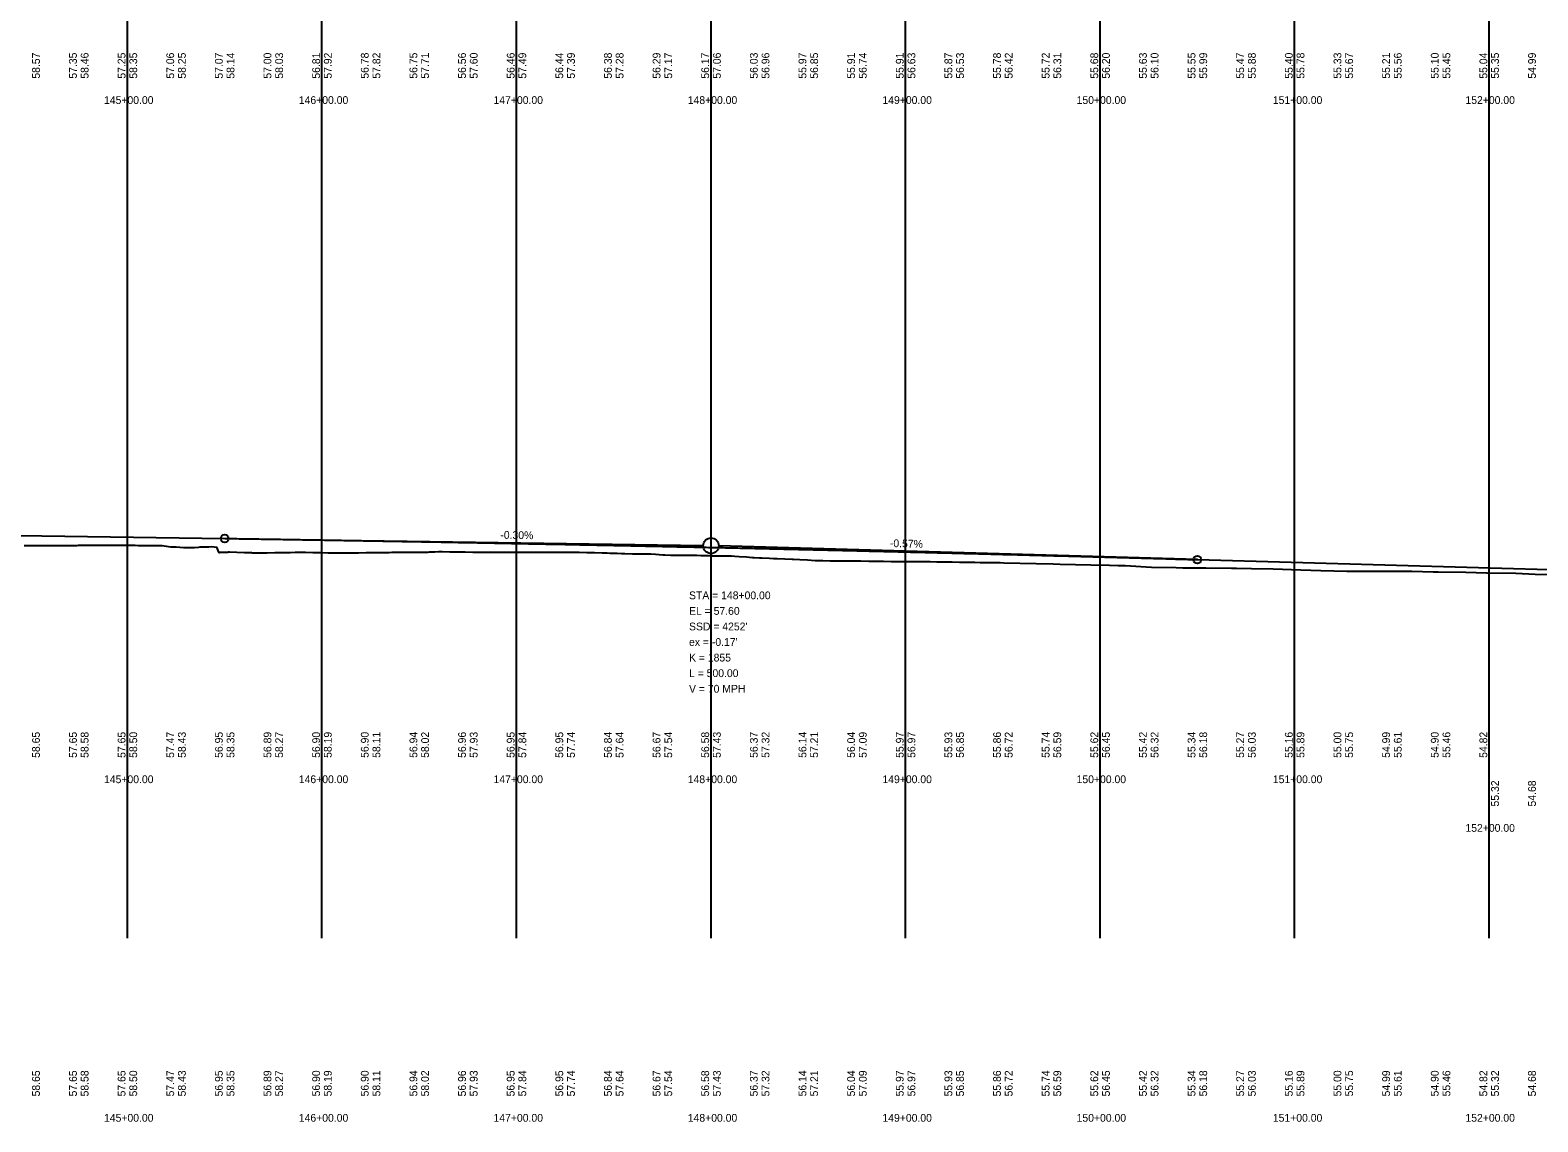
# Model space of a CAD drawing. Extents: x 3880794 to 3915434, y 287517 to 300173.
# Drawn here: x 3913601 to 3914376, y 292382 to 292943 of the extents above; entities that cross this region are included whole.
import ezdxf

# ---------------------------------------------------------------- set-up
doc = ezdxf.new("R2010")
doc.units = 0
for name, color, linetype in [('Level 1', 7, 'Continuous'), ('Level 30', 7, 'Continuous'), ('Level 31', 7, 'Continuous'), ('Level 32', 7, 'Continuous')]:
    doc.layers.add(name, color=color, linetype=linetype)

msp = doc.modelspace()

# ---------------------------------------------------------------- linework, layer by layer
at = {"layer": 'Level 1'}
for p, q in [((3913651.21, 292476.49), (3913651.21, 293504.13)), ((3913751.21, 292476.49), (3913751.21, 293504.13)), ((3913851.21, 292476.49), (3913851.21, 293504.13)), ((3913951.21, 292476.49), (3913951.21, 293504.13)), ((3914051.21, 292476.49), (3914051.21, 293504.13)), ((3914151.21, 292476.49), (3914151.21, 293504.13)), ((3914251.21, 292476.49), (3914251.21, 293504.13)), ((3914351.21, 292476.49), (3914351.21, 293504.13)), ((3913401.21, 292686.36), (3913701.21, 292681.86)), ((3913701.21, 292681.86), (3913947.21, 292678.17)), ((3914201.21, 292670.99), (3913955.21, 292678)), ((3914201.21, 292670.99), (3914552.78, 292660.98))]:
    msp.add_line(p, q, dxfattribs=at)
for points in [[(3913598.07, 292678.27), (3913601.89, 292678.23), (3913605.8, 292678.24), (3913609.71, 292678.26), (3913613.62, 292678.31), (3913617.53, 292678.3), (3913621.44, 292678.31), (3913625.35, 292678.33), (3913626.01, 292678.34), (3913628.74, 292678.38), (3913629.26, 292678.38), (3913633.17, 292678.37), (3913637.09, 292678.37), (3913641, 292678.39), (3913641.31, 292678.39), (3913642.66, 292678.37), (3913644.91, 292678.36), (3913648.82, 292678.34), (3913652.73, 292678.34), (3913655.2, 292678.35), (3913656.65, 292678.31), (3913660.55, 292678.27), (3913664.46, 292678.25), (3913668.37, 292678.25), (3913669.06, 292678.25), (3913672.28, 292677.77), (3913673.54, 292677.59), (3913676.19, 292677.48), (3913680.1, 292677.22), (3913680.77, 292677.18), (3913684.02, 292677.16), (3913685.68, 292677.15), (3913687.93, 292677.45), (3913688.68, 292677.56), (3913691.84, 292677.59), (3913693.07, 292677.61), (3913694.36, 292677.68), (3913695.75, 292677.53), (3913696.94, 292677.42), (3913698.03, 292674.77), (3913698.46, 292674.72), (3913698.97, 292674.77), (3913699.66, 292674.8), (3913701.44, 292674.89), (3913702.47, 292674.88)], [(3913702.47, 292674.88), (3913702.78, 292674.85), (3913703.1, 292674.94), (3913703.68, 292675.03), (3913707.48, 292674.87), (3913711.39, 292674.71), (3913714.91, 292674.57), (3913715.3, 292674.54), (3913717.98, 292674.4), (3913719.21, 292674.42), (3913723.12, 292674.5), (3913727.03, 292674.58), (3913730.95, 292674.66), (3913734.86, 292674.73), (3913737.39, 292674.78), (3913737.75, 292674.78), (3913738.77, 292674.8), (3913739.37, 292674.81), (3913740.12, 292674.8), (3913742.68, 292674.76), (3913746.59, 292674.69), (3913750.5, 292674.63), (3913754.41, 292674.56), (3913758.32, 292674.49), (3913762.23, 292674.42), (3913762.76, 292674.41), (3913763.37, 292674.43), (3913766.14, 292674.47), (3913770.05, 292674.53), (3913773.96, 292674.58), (3913777.88, 292674.63), (3913781.79, 292674.68), (3913783.74, 292674.69), (3913785.7, 292674.73), (3913787.05, 292674.76), (3913789.61, 292674.77), (3913793.52, 292674.77), (3913797.43, 292674.78), (3913801.34, 292674.79), (3913805.25, 292674.8), (3913805.88, 292674.8), (3913806.5, 292674.94), (3913807.08, 292674.96), (3913809.16, 292675.04), (3913811.06, 292675.12), (3913813.07, 292675.09), (3913816.98, 292675.04), (3913820.89, 292674.99), (3913824.8, 292674.94), (3913828.72, 292674.88), (3913831.94, 292674.83), (3913832.63, 292674.83), (3913836.54, 292674.84), (3913837.4, 292674.84), (3913840.45, 292674.84), (3913844.36, 292674.85), (3913848.27, 292674.85), (3913852.18, 292674.85), (3913855.01, 292674.85), (3913856.09, 292674.86), (3913860, 292674.89), (3913862.01, 292674.9), (3913863.91, 292674.9), (3913867.82, 292674.9), (3913871.73, 292674.9), (3913873.09, 292674.89), (3913875.65, 292674.87), (3913879.56, 292674.84), (3913882.02, 292674.82), (3913883.47, 292674.78), (3913887.38, 292674.69), (3913891.29, 292674.59), (3913895.2, 292674.49), (3913897.74, 292674.42), (3913899.11, 292674.39), (3913899.81, 292674.37), (3913903.02, 292674.22), (3913905.17, 292674.12), (3913906.93, 292674.1), (3913910.84, 292674.04), (3913914.75, 292673.99), (3913918.66, 292673.93), (3913920.2, 292673.91), (3913922.58, 292673.72), (3913926.49, 292673.42), (3913926.96, 292673.38), (3913927.48, 292673.38), (3913930.4, 292673.35), (3913934.31, 292673.31), (3913935.21, 292673.3), (3913938.22, 292673.27), (3913942.13, 292673.23), (3913943.87, 292673.21), (3913946.04, 292673.15), (3913949.95, 292673.03), (3913951.86, 292672.98), (3913952.93, 292672.94), (3913953.86, 292672.96), (3913954.42, 292672.97), (3913957.77, 292672.92), (3913961.68, 292672.86)], [(3913961.68, 292672.86), (3913963.5, 292672.83), (3913965.59, 292672.67), (3913969.51, 292672.37), (3913972.47, 292672.14), (3913973.42, 292672.09), (3913976.05, 292671.95), (3913977.33, 292671.88), (3913981.24, 292671.66), (3913983.27, 292671.54), (3913985.15, 292671.49), (3913989.1, 292671.36), (3913992.97, 292671.3), (3913993.54, 292671.29), (3913996.88, 292671.08), (3914000.79, 292670.84), (3914004.7, 292670.59), (3914005.34, 292670.55), (3914008.61, 292670.5), (3914012.52, 292670.45), (3914016.44, 292670.4), (3914018.47, 292670.37), (3914020.35, 292670.34), (3914024.26, 292670.31), (3914028.17, 292670.28), (3914032.37, 292670.25), (3914035.99, 292670.18), (3914039.9, 292670.12), (3914043.81, 292670.05), (3914044.79, 292670.03), (3914045.16, 292670.03), (3914047.72, 292669.99), (3914048.78, 292669.97), (3914051.63, 292669.96), (3914055.54, 292669.96), (3914059.45, 292669.95), (3914062.69, 292669.94), (3914063.36, 292669.94), (3914063.88, 292669.94), (3914067.28, 292669.89), (3914071.19, 292669.83), (3914073.15, 292669.8), (3914075.1, 292669.77), (3914079.01, 292669.72), (3914082.92, 292669.67), (3914086.83, 292669.62), (3914089.62, 292669.58), (3914090.74, 292669.57), (3914097.74, 292669.46), (3914099.76, 292669.43), (3914101.74, 292669.38), (3914118.25, 292669.01), (3914127.04, 292668.78), (3914130.68, 292668.7), (3914146.48, 292668.31), (3914155.99, 292668.07), (3914160.46, 292667.95), (3914164.09, 292667.9), (3914177.58, 292667.13), (3914190.27, 292666.97), (3914193.78, 292666.8), (3914205.54, 292666.78), (3914218.81, 292666.61), (3914221.3, 292666.61), (3914228.94, 292666.41), (3914240.14, 292666.19), (3914254.37, 292665.82), (3914264.66, 292665.39), (3914278.05, 292665.04), (3914289.44, 292665.1), (3914295.64, 292665.07), (3914297.41, 292665.08), (3914311.45, 292665.01), (3914322.36, 292664.71), (3914324.91, 292664.64), (3914339.28, 292664.57), (3914349.76, 292664.23), (3914350.1, 292664.22), (3914364.82, 292663.98), (3914374.84, 292663.54), (3914388.56, 292663.32)]]:
    msp.add_lwpolyline(points, dxfattribs=at)
msp.add_circle((3913951.21, 292678.11), 4, dxfattribs=at)
msp.add_spline([(3913701.21, 292681.86), (3913711.21, 292681.71), (3913721.21, 292681.55), (3913731.21, 292681.4), (3913741.21, 292681.24), (3913751.21, 292681.08), (3913761.21, 292680.91), (3913771.21, 292680.74), (3913781.21, 292680.57), (3913791.21, 292680.4), (3913801.21, 292680.22), (3913811.21, 292680.05), (3913821.21, 292679.86), (3913831.21, 292679.68), (3913841.21, 292679.49), (3913851.21, 292679.31), (3913861.21, 292679.11), (3913871.21, 292678.92), (3913881.21, 292678.72), (3913891.21, 292678.52), (3913901.21, 292678.32), (3913911.21, 292678.11), (3913921.21, 292677.91), (3913931.21, 292677.7), (3913941.21, 292677.48), (3913951.21, 292677.27), (3913961.21, 292677.05), (3913971.21, 292676.83), (3913981.21, 292676.6), (3913991.21, 292676.38), (3914001.21, 292676.15), (3914011.21, 292675.91), (3914021.21, 292675.68), (3914031.21, 292675.44), (3914041.21, 292675.2), (3914051.21, 292674.96), (3914061.21, 292674.71), (3914071.21, 292674.46), (3914081.21, 292674.21), (3914091.21, 292673.96), (3914101.21, 292673.7), (3914111.21, 292673.44), (3914121.21, 292673.18), (3914131.21, 292672.92), (3914141.21, 292672.65), (3914151.21, 292672.38), (3914161.21, 292672.11), (3914171.21, 292671.83), (3914181.21, 292671.55), (3914191.21, 292671.27), (3914201.21, 292670.99)], degree=3, dxfattribs=at)
at = {"layer": 'Level 31'}
for centre in [(3913701.21, 292681.86), (3914201.21, 292670.99)]:
    msp.add_circle(centre, 2, dxfattribs=at)

# ---------------------------------------------------------------- texts
at = {"layer": 'Level 30'}
for s, p in [('145+00.00', (3913639.18, 292905.16)), ('145+00.00', (3913639.18, 292905.16)), ('146+00.00', (3913739.31, 292905.16)), ('146+00.00', (3913739.31, 292905.16)), ('147+00.00', (3913839.4, 292905.16)), ('147+00.00', (3913839.4, 292905.16)), ('148+00.00', (3913939.25, 292905.16)), ('148+00.00', (3913939.25, 292905.16)), ('149+00.00', (3914039.31, 292905.16)), ('149+00.00', (3914039.31, 292905.16)), ('150+00.00', (3914139.12, 292905.16)), ('150+00.00', (3914139.12, 292905.16)), ('151+00.00', (3914240, 292905.16)), ('151+00.00', (3914240, 292905.16)), ('152+00.00', (3914338.99, 292905.16)), ('152+00.00', (3914338.99, 292905.16)), ('145+00.00', (3913639.18, 292556.11)), ('145+00.00', (3913639.18, 292556.11)), ('146+00.00', (3913739.31, 292556.11)), ('146+00.00', (3913739.31, 292556.11)), ('147+00.00', (3913839.4, 292556.11)), ('147+00.00', (3913839.4, 292556.11)), ('148+00.00', (3913939.25, 292556.11)), ('148+00.00', (3913939.25, 292556.11)), ('149+00.00', (3914039.31, 292556.11)), ('149+00.00', (3914039.31, 292556.11)), ('150+00.00', (3914139.12, 292556.11)), ('150+00.00', (3914139.12, 292556.11)), ('151+00.00', (3914240, 292556.11)), ('151+00.00', (3914240, 292556.11)), ('152+00.00', (3914338.99, 292531.11)), ('152+00.00', (3914338.99, 292531.11)), ('145+00.00', (3913639.18, 292382.11)), ('145+00.00', (3913639.18, 292382.11)), ('146+00.00', (3913739.31, 292382.11)), ('146+00.00', (3913739.31, 292382.11)), ('147+00.00', (3913839.4, 292382.11)), ('147+00.00', (3913839.4, 292382.11)), ('148+00.00', (3913939.25, 292382.11)), ('148+00.00', (3913939.25, 292382.11)), ('149+00.00', (3914039.31, 292382.11)), ('149+00.00', (3914039.31, 292382.11)), ('150+00.00', (3914139.12, 292382.11)), ('150+00.00', (3914139.12, 292382.11)), ('151+00.00', (3914240, 292382.11)), ('151+00.00', (3914240, 292382.11)), ('152+00.00', (3914338.99, 292382.11)), ('152+00.00', (3914338.99, 292382.11))]:
    msp.add_text(s, height=4, dxfattribs=at).set_placement(p)
at = {"layer": 'Level 31'}
for s, rotation, p in [('-0.30%', 359.14063, (3913842.88, 292681.73)), ('-0.57%', 358.3687, (3914043.11, 292677.49)), ('58.65', 90, (3913606.21, 292569.11)), ('57.65', 90, (3913625.21, 292569.11)), ('58.58', 90, (3913631.21, 292569.11)), ('57.65', 90, (3913650.21, 292569.11)), ('58.50', 90, (3913656.21, 292569.11)), ('57.47', 90, (3913675.21, 292569.11)), ('58.43', 90, (3913681.21, 292569.11)), ('56.95', 90, (3913700.21, 292569.11)), ('58.35', 90, (3913706.21, 292569.11)), ('56.89', 90, (3913725.21, 292569.11)), ('58.27', 90, (3913731.21, 292569.11)), ('56.90', 90, (3913750.21, 292569.11)), ('58.19', 90, (3913756.21, 292569.11)), ('56.90', 90, (3913775.21, 292569.11)), ('58.11', 90, (3913781.21, 292569.11)), ('56.94', 90, (3913800.21, 292569.11)), ('58.02', 90, (3913806.21, 292569.11)), ('56.96', 90, (3913825.21, 292569.11)), ('57.93', 90, (3913831.21, 292569.11)), ('56.95', 90, (3913850.21, 292569.11)), ('57.84', 90, (3913856.21, 292569.11)), ('56.95', 90, (3913875.21, 292569.11)), ('57.74', 90, (3913881.21, 292569.11)), ('56.84', 90, (3913900.21, 292569.11)), ('57.64', 90, (3913906.21, 292569.11)), ('56.67', 90, (3913925.21, 292569.11)), ('57.54', 90, (3913931.21, 292569.11)), ('56.58', 90, (3913950.21, 292569.11)), ('57.43', 90, (3913956.21, 292569.11)), ('56.37', 90, (3913975.21, 292569.11)), ('57.32', 90, (3913981.21, 292569.11)), ('56.14', 90, (3914000.21, 292569.11)), ('57.21', 90, (3914006.21, 292569.11)), ('56.04', 90, (3914025.21, 292569.11)), ('57.09', 90, (3914031.21, 292569.11)), ('55.97', 90, (3914050.21, 292569.11)), ('56.97', 90, (3914056.21, 292569.11)), ('55.93', 90, (3914075.21, 292569.11)), ('56.85', 90, (3914081.21, 292569.11)), ('55.86', 90, (3914100.21, 292569.11)), ('56.72', 90, (3914106.21, 292569.11)), ('55.74', 90, (3914125.21, 292569.11)), ('56.59', 90, (3914131.21, 292569.11)), ('55.62', 90, (3914150.21, 292569.11)), ('56.45', 90, (3914156.21, 292569.11)), ('55.42', 90, (3914175.21, 292569.11)), ('56.32', 90, (3914181.21, 292569.11)), ('55.34', 90, (3914200.21, 292569.11)), ('56.18', 90, (3914206.21, 292569.11)), ('55.27', 90, (3914225.21, 292569.11)), ('56.03', 90, (3914231.21, 292569.11)), ('55.16', 90, (3914250.21, 292569.11)), ('55.89', 90, (3914256.21, 292569.11)), ('55.00', 90, (3914275.21, 292569.11)), ('55.75', 90, (3914281.21, 292569.11)), ('54.99', 90, (3914300.21, 292569.11)), ('55.61', 90, (3914306.21, 292569.11)), ('54.90', 90, (3914325.21, 292569.11)), ('55.46', 90, (3914331.21, 292569.11)), ('54.82', 90, (3914350.21, 292569.11)), ('55.32', 90, (3914356.21, 292544.11)), ('54.68', 90, (3914375.21, 292544.11)), ('58.65', 90, (3913606.21, 292395.11)), ('57.65', 90, (3913625.21, 292395.11)), ('58.58', 90, (3913631.21, 292395.11)), ('57.65', 90, (3913650.21, 292395.11)), ('58.50', 90, (3913656.21, 292395.11)), ('57.47', 90, (3913675.21, 292395.11)), ('58.43', 90, (3913681.21, 292395.11)), ('56.95', 90, (3913700.21, 292395.11)), ('58.35', 90, (3913706.21, 292395.11)), ('56.89', 90, (3913725.21, 292395.11)), ('58.27', 90, (3913731.21, 292395.11)), ('56.90', 90, (3913750.21, 292395.11)), ('58.19', 90, (3913756.21, 292395.11)), ('56.90', 90, (3913775.21, 292395.11)), ('58.11', 90, (3913781.21, 292395.11)), ('56.94', 90, (3913800.21, 292395.11)), ('58.02', 90, (3913806.21, 292395.11)), ('56.96', 90, (3913825.21, 292395.11)), ('57.93', 90, (3913831.21, 292395.11)), ('56.95', 90, (3913850.21, 292395.11)), ('57.84', 90, (3913856.21, 292395.11)), ('56.95', 90, (3913875.21, 292395.11)), ('57.74', 90, (3913881.21, 292395.11)), ('56.84', 90, (3913900.21, 292395.11)), ('57.64', 90, (3913906.21, 292395.11)), ('56.67', 90, (3913925.21, 292395.11)), ('57.54', 90, (3913931.21, 292395.11)), ('56.58', 90, (3913950.21, 292395.11)), ('57.43', 90, (3913956.21, 292395.11)), ('56.37', 90, (3913975.21, 292395.11)), ('57.32', 90, (3913981.21, 292395.11)), ('56.14', 90, (3914000.21, 292395.11)), ('57.21', 90, (3914006.21, 292395.11)), ('56.04', 90, (3914025.21, 292395.11)), ('57.09', 90, (3914031.21, 292395.11)), ('55.97', 90, (3914050.21, 292395.11)), ('56.97', 90, (3914056.21, 292395.11)), ('55.93', 90, (3914075.21, 292395.11)), ('56.85', 90, (3914081.21, 292395.11)), ('55.86', 90, (3914100.21, 292395.11)), ('56.72', 90, (3914106.21, 292395.11)), ('55.74', 90, (3914125.21, 292395.11)), ('56.59', 90, (3914131.21, 292395.11)), ('55.62', 90, (3914150.21, 292395.11)), ('56.45', 90, (3914156.21, 292395.11)), ('55.42', 90, (3914175.21, 292395.11)), ('56.32', 90, (3914181.21, 292395.11)), ('55.34', 90, (3914200.21, 292395.11)), ('56.18', 90, (3914206.21, 292395.11)), ('55.27', 90, (3914225.21, 292395.11)), ('56.03', 90, (3914231.21, 292395.11)), ('55.16', 90, (3914250.21, 292395.11)), ('55.89', 90, (3914256.21, 292395.11)), ('55.00', 90, (3914275.21, 292395.11)), ('55.75', 90, (3914281.21, 292395.11)), ('54.99', 90, (3914300.21, 292395.11)), ('55.61', 90, (3914306.21, 292395.11)), ('54.90', 90, (3914325.21, 292395.11)), ('55.46', 90, (3914331.21, 292395.11)), ('54.82', 90, (3914350.21, 292395.11)), ('55.32', 90, (3914356.21, 292395.11)), ('54.68', 90, (3914375.21, 292395.11))]:
    msp.add_text(s, height=4, rotation=rotation, dxfattribs=at).set_placement(p)
for s, p in [('STA = 148+00.00', (3913939.9, 292650.63)), ('EL = 57.60', (3913939.9, 292642.63)), ("SSD = 4252'", (3913939.9, 292634.63)), ("ex = -0.17'", (3913939.9, 292626.63)), ('K = 1855', (3913939.9, 292618.63)), ('L = 500.00', (3913939.9, 292610.63)), ('V = 70 MPH', (3913939.9, 292602.63))]:
    msp.add_text(s, height=4, dxfattribs=at).set_placement(p)
at = {"layer": 'Level 32'}
for s, p in [('58.57', (3913606.21, 292918.16)), ('57.35', (3913625.21, 292918.16)), ('58.46', (3913631.21, 292918.16)), ('57.25', (3913650.21, 292918.16)), ('58.35', (3913656.21, 292918.16)), ('57.06', (3913675.21, 292918.16)), ('58.25', (3913681.21, 292918.16)), ('57.07', (3913700.21, 292918.16)), ('58.14', (3913706.21, 292918.16)), ('57.00', (3913725.21, 292918.16)), ('58.03', (3913731.21, 292918.16)), ('56.81', (3913750.21, 292918.16)), ('57.92', (3913756.21, 292918.16)), ('56.78', (3913775.21, 292918.16)), ('57.82', (3913781.21, 292918.16)), ('56.75', (3913800.21, 292918.16)), ('57.71', (3913806.21, 292918.16)), ('56.56', (3913825.21, 292918.16)), ('57.60', (3913831.21, 292918.16)), ('56.46', (3913850.21, 292918.16)), ('57.49', (3913856.21, 292918.16)), ('56.44', (3913875.21, 292918.16)), ('57.39', (3913881.21, 292918.16)), ('56.38', (3913900.21, 292918.16)), ('57.28', (3913906.21, 292918.16)), ('56.29', (3913925.21, 292918.16)), ('57.17', (3913931.21, 292918.16)), ('56.17', (3913950.21, 292918.16)), ('57.06', (3913956.21, 292918.16)), ('56.03', (3913975.21, 292918.16)), ('56.96', (3913981.21, 292918.16)), ('55.97', (3914000.21, 292918.16)), ('56.85', (3914006.21, 292918.16)), ('55.91', (3914025.21, 292918.16)), ('56.74', (3914031.21, 292918.16)), ('55.91', (3914050.21, 292918.16)), ('56.63', (3914056.21, 292918.16)), ('55.87', (3914075.21, 292918.16)), ('56.53', (3914081.21, 292918.16)), ('55.78', (3914100.21, 292918.16)), ('56.42', (3914106.21, 292918.16)), ('55.72', (3914125.21, 292918.16)), ('56.31', (3914131.21, 292918.16)), ('55.68', (3914150.21, 292918.16)), ('56.20', (3914156.21, 292918.16)), ('55.63', (3914175.21, 292918.16)), ('56.10', (3914181.21, 292918.16)), ('55.55', (3914200.21, 292918.16)), ('55.99', (3914206.21, 292918.16)), ('55.47', (3914225.21, 292918.16)), ('55.88', (3914231.21, 292918.16)), ('55.40', (3914250.21, 292918.16)), ('55.78', (3914256.21, 292918.16)), ('55.33', (3914275.21, 292918.16)), ('55.67', (3914281.21, 292918.16)), ('55.21', (3914300.21, 292918.16)), ('55.56', (3914306.21, 292918.16)), ('55.10', (3914325.21, 292918.16)), ('55.45', (3914331.21, 292918.16)), ('55.04', (3914350.21, 292918.16)), ('55.35', (3914356.21, 292918.16)), ('54.99', (3914375.21, 292918.16))]:
    msp.add_text(s, height=4, rotation=90, dxfattribs=at).set_placement(p)

doc.saveas('drawing.dxf')
